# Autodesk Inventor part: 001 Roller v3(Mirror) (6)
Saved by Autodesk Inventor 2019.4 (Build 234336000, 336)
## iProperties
Created: 2020-06
Part Number: 001 Roller v3(Mirror) (6)
Material: Generic
Document SubType Name: Modeling
Designer: Administrator
Density: 1 g/cm^3
Appearance: Default
Title: 001 Roller v3(Mirror) (6)
Author: Administrator
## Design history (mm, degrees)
